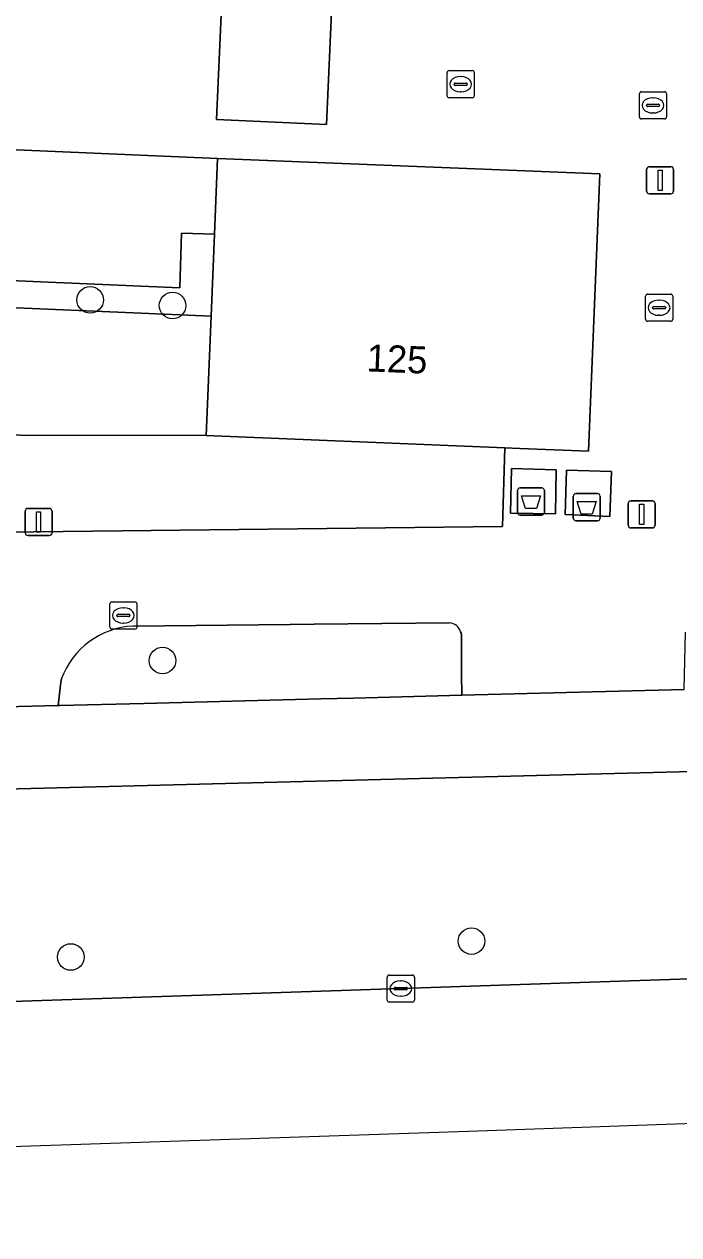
# Model space of a CAD drawing. Extents: x 160888 to 161385, y 386490 to 386908.
# Drawn here: x 161181.1 to 161205.21, y 386494.25 to 386538.84 of the extents above; entities that cross this region are included whole.
import ezdxf

# ---------------------------------------------------------------- set-up
doc = ezdxf.new("R2010")
doc.units = 0
for name, color, linetype in [('IMGEO_Afval_apart_plaats', 7, 'Continuous'), ('IMGEO_Berm_groen', 7, 'Continuous'), ('IMGEO_Boom', 7, 'Continuous'), ('IMGEO_Fietspad_gesloten', 7, 'Continuous'), ('IMGEO_Groenvoorziening', 7, 'Continuous'), ('IMGEO_Haag', 7, 'Continuous'), ('IMGEO_Kolk', 7, 'Continuous'), ('IMGEO_Lichtmast', 7, 'Continuous'), ('IMGEO_Pand', 7, 'Continuous'), ('IMGEO_Pand_nummerreeks', 7, 'Continuous'), ('IMGEO_Parkeervlak_open', 7, 'Continuous'), ('IMGEO_Rijbaan_lokaal_open', 7, 'Continuous'), ('IMGEO_Rijbaan_regionaal_gesloten', 7, 'Continuous'), ('IMGEO_Rioolput', 7, 'Continuous'), ('IMGEO_Voetgangersgebied_open', 7, 'Continuous'), ('IMGEO_Voetpad_gesloten', 7, 'Continuous')]:
    doc.layers.add(name, color=color, linetype=linetype)

msp = doc.modelspace()

# ---------------------------------------------------------------- linework, layer by layer
at = {"layer": 'IMGEO_Afval_apart_plaats'}
for p, q in [((161199.27, 386520.86), (161199.27, 386521.66)), ((161199.27, 386521.66), (161199.27, 386520.86)), ((161199.37, 386521.76), (161200.16, 386521.76)), ((161200.16, 386521.76), (161199.37, 386521.76)), ((161200.26, 386521.66), (161200.26, 386520.86)), ((161200.26, 386520.86), (161200.26, 386521.66)), ((161201.323, 386520.65), (161201.323, 386521.45)), ((161201.323, 386521.45), (161201.323, 386520.65)), ((161201.423, 386521.55), (161202.213, 386521.55)), ((161202.213, 386521.55), (161201.423, 386521.55)), ((161202.313, 386521.45), (161202.313, 386520.65)), ((161202.313, 386520.65), (161202.313, 386521.45)), ((161200.16, 386520.76), (161199.37, 386520.76)), ((161199.37, 386520.76), (161200.16, 386520.76)), ((161202.213, 386520.55), (161201.423, 386520.55)), ((161201.423, 386520.55), (161202.213, 386520.55))]:
    msp.add_line(p, q, dxfattribs=at)
for points in [[(161199.413, 386521.474), (161200.117, 386521.474), (161199.968, 386521.004), (161199.562, 386521.004), (161199.413, 386521.474)], [(161201.466, 386521.264), (161202.17, 386521.264), (161202.021, 386520.794), (161201.615, 386520.794), (161201.466, 386521.264)]]:
    msp.add_lwpolyline(points, dxfattribs=at)
for centre, start, end in [((161199.37, 386521.66), 90, 180), ((161199.37, 386521.66), 90, 180), ((161200.16, 386521.66), 0, 90), ((161200.16, 386521.66), 360, 90), ((161201.423, 386521.45), 90, 180), ((161201.423, 386521.45), 90, 180), ((161202.213, 386521.45), 0, 90), ((161202.213, 386521.45), 360, 90), ((161199.37, 386520.86), 180, 270), ((161199.37, 386520.86), 180, 270), ((161200.16, 386520.86), 270, 0), ((161200.16, 386520.86), 270, 0), ((161201.423, 386520.65), 180, 270), ((161201.423, 386520.65), 180, 270), ((161202.213, 386520.65), 270, 0), ((161202.213, 386520.65), 270, 0)]:
    msp.add_arc(centre, 0.1, start, end, dxfattribs=at)
at = {"layer": 'IMGEO_Berm_groen'}
for points in [[(161313.071, 386509.592), (161311.776, 386509.705), (161311.73, 386509.285), (161306.097, 386509.668), (161267.164, 386511.376), (161259.697, 386511.429), (161237.753, 386511.488), (161222.805, 386511.284), (161215.758, 386511.159), (161215.734, 386511.569), (161167.964, 386510.348), (161127.225, 386509.29)], [(161133.563, 386501.204), (161154.024, 386501.918), (161175.497, 386502.675), (161194.971, 386503.319), (161214.429, 386503.969), (161233.906, 386504.66), (161254.372, 386505.373), (161273.833, 386506.048), (161292.306, 386506.7), (161322.733, 386507.751)]]:
    msp.add_lwpolyline(points, dxfattribs=at)
at = {"layer": 'IMGEO_Boom'}
for centre in [(161183.527, 386528.686), (161186.565, 386528.479), (161186.191, 386515.403), (161197.575, 386505.068), (161182.817, 386504.482)]:
    msp.add_circle(centre, 0.489, dxfattribs=at)
at = {"layer": 'IMGEO_Fietspad_gesloten'}
for points in [[(161205.404, 386514.331), (161197.221, 386514.122), (161193.677, 386514.032), (161193.234, 386514.02), (161192.022, 386513.989), (161185.501, 386513.823), (161182.4, 386513.744), (161182.354, 386513.743), (161179.426, 386513.668), (161167.488, 386513.363), (161165.011, 386513.3), (161158.3, 386513.129), (161154.404, 386513.03), (161149.878, 386512.914), (161142.637, 386512.729), (161139.461, 386512.648)], [(161106.833, 386506.491), (161109.839, 386506.955), (161116.836, 386508.035), (161123.035, 386508.931), (161127.225, 386509.29), (161167.964, 386510.348), (161215.734, 386511.569), (161215.758, 386511.159), (161222.805, 386511.284), (161237.753, 386511.488), (161259.697, 386511.429), (161267.164, 386511.376), (161306.097, 386509.668), (161311.73, 386509.285), (161311.776, 386509.705), (161313.071, 386509.592)]]:
    msp.add_lwpolyline(points, dxfattribs=at)
at = {"layer": 'IMGEO_Groenvoorziening'}
for points in [[(161188.104, 386531.103), (161186.895, 386531.144), (161186.834, 386529.132), (161153.546, 386530.566), (161144.394, 386530.967), (161144.63, 386535.735), (161143.433, 386535.771), (161143.157, 386530.019), (161167.323, 386528.975), (161187.983, 386528.081)], [(161187.807, 386523.685), (161187.983, 386528.081), (161167.323, 386528.975), (161167.064, 386523.737), (161174.072, 386523.72)], [(161198.801, 386523.24), (161187.807, 386523.685), (161174.072, 386523.72), (161173.891, 386520.061), (161198.713, 386520.334)]]:
    msp.add_lwpolyline(points, close=True, dxfattribs=at)
for points in [[(161196.762, 386516.787), (161191.781, 386516.739), (161190.894, 386516.73), (161185.113, 386516.671)], [(161182.354, 386513.743), (161182.4, 386513.744), (161185.501, 386513.823), (161192.022, 386513.989), (161193.234, 386514.02), (161193.677, 386514.032), (161197.221, 386514.122), (161197.21, 386514.917), (161197.209, 386515.225), (161197.205, 386516.146), (161197.204, 386516.312), (161197.201, 386516.355), (161197.194, 386516.396), (161197.188, 386516.423), (161197.175, 386516.465)], [(161182.475, 386514.735), (161182.438, 386514.506), (161182.354, 386513.743)]]:
    msp.add_lwpolyline(points, dxfattribs=at)
for centre, radius, start, end in [((161196.737, 386516.329), 0.459, 17.2537, 86.862), ((161185.259, 386513.707), 2.967, 92.8126, 159.7365)]:
    msp.add_arc(centre, radius, start, end, dxfattribs=at)
at = {"layer": 'IMGEO_Haag'}
msp.add_lwpolyline([(161188.104, 386531.103), (161186.895, 386531.144), (161186.834, 386529.132), (161153.546, 386530.566), (161144.394, 386530.967), (161144.63, 386535.735), (161143.433, 386535.771), (161143.157, 386530.019), (161167.323, 386528.975), (161187.983, 386528.081)], close=True, dxfattribs=at)
at = {"layer": 'IMGEO_Kolk'}
for p, q in [((161196.677, 386536.204), (161196.677, 386537.056)), ((161196.752, 386537.13), (161197.604, 386537.13)), ((161197.165, 386536.91), (161197.19, 386536.91)), ((161197.678, 386537.056), (161197.678, 386536.204)), ((161196.936, 386536.624), (161196.936, 386536.636)), ((161197.374, 386536.587), (161196.976, 386536.587)), ((161196.979, 386536.673), (161197.377, 386536.673)), ((161197.188, 386536.35), (161197.163, 386536.35)), ((161197.42, 386536.636), (161197.42, 386536.624)), ((161197.604, 386536.13), (161196.752, 386536.13)), ((161203.984, 386527.972), (161203.984, 386528.824)), ((161204.059, 386528.898), (161204.911, 386528.898)), ((161204.985, 386528.824), (161204.985, 386527.972)), ((161204.243, 386528.392), (161204.243, 386528.404)), ((161204.681, 386528.355), (161204.283, 386528.355)), ((161204.286, 386528.441), (161204.684, 386528.441)), ((161204.472, 386528.678), (161204.497, 386528.678)), ((161204.727, 386528.404), (161204.727, 386528.392)), ((161204.911, 386527.898), (161204.059, 386527.898)), ((161204.495, 386528.118), (161204.47, 386528.118)), ((161184.253, 386516.637), (161184.253, 386517.489)), ((161184.328, 386517.563), (161185.18, 386517.563)), ((161184.741, 386517.343), (161184.766, 386517.343)), ((161185.254, 386517.489), (161185.254, 386516.637)), ((161184.512, 386517.057), (161184.512, 386517.069)), ((161184.95, 386517.02), (161184.552, 386517.02)), ((161184.555, 386517.106), (161184.953, 386517.106)), ((161184.764, 386516.783), (161184.739, 386516.783)), ((161184.996, 386517.069), (161184.996, 386517.057)), ((161185.18, 386516.563), (161184.328, 386516.563)), ((161194.545, 386503.819), (161195.397, 386503.819)), ((161194.47, 386502.893), (161194.47, 386503.745)), ((161194.729, 386503.313), (161194.729, 386503.325)), ((161194.772, 386503.362), (161195.17, 386503.362)), ((161194.958, 386503.599), (161194.983, 386503.599)), ((161195.213, 386503.325), (161195.213, 386503.313)), ((161195.471, 386503.745), (161195.471, 386502.893)), ((161195.167, 386503.276), (161194.769, 386503.276)), ((161194.981, 386503.039), (161194.956, 386503.039)), ((161195.397, 386502.819), (161194.545, 386502.819))]:
    msp.add_line(p, q, dxfattribs=at)
for points in [[(161196.677, 386536.204), (161196.677, 386537.056)], [(161196.752, 386537.13), (161197.604, 386537.13)], [(161197.678, 386537.056), (161197.678, 386536.204)], [(161197.604, 386536.13), (161196.752, 386536.13)], [(161203.984, 386527.972), (161203.984, 386528.824)], [(161204.059, 386528.898), (161204.911, 386528.898)], [(161204.985, 386528.824), (161204.985, 386527.972)], [(161204.911, 386527.898), (161204.059, 386527.898)], [(161184.253, 386516.637), (161184.253, 386517.489)], [(161184.328, 386517.563), (161185.18, 386517.563)], [(161185.254, 386517.489), (161185.254, 386516.637)], [(161185.18, 386516.563), (161184.328, 386516.563)], [(161194.545, 386503.819), (161195.397, 386503.819)], [(161194.47, 386502.893), (161194.47, 386503.745)], [(161195.471, 386503.745), (161195.471, 386502.893)], [(161195.397, 386502.819), (161194.545, 386502.819)]]:
    msp.add_lwpolyline(points, dxfattribs=at)
for centre, radius, start, end in [((161196.754, 386537.054), 0.0765, 91.552, 178.448), ((161196.754, 386537.054), 0.0765, 91.552, 178.448), ((161197.602, 386537.054), 0.0765, 1.552, 88.448), ((161197.602, 386537.054), 0.0765, 1.552, 88.448), ((161196.976, 386536.633), 0.0403, 85.8775, 175.7526), ((161196.973, 386536.623), 0.0366, 178.938, 274.7102), ((161197.377, 386536.63), 0.043, 264.8664, 352.4533), ((161197.381, 386536.635), 0.0386, 1.7309, 96.639), ((161196.754, 386536.206), 0.0765, 181.552, 268.448), ((161196.754, 386536.206), 0.0765, 181.552, 268.448), ((161197.602, 386536.206), 0.0765, 271.552, 358.448), ((161197.602, 386536.206), 0.0765, 271.552, 358.448), ((161204.061, 386528.822), 0.0765, 91.552, 178.448), ((161204.061, 386528.822), 0.0765, 91.552, 178.448), ((161204.909, 386528.822), 0.0765, 1.552, 88.448), ((161204.909, 386528.822), 0.0765, 1.552, 88.448), ((161204.283, 386528.401), 0.0403, 85.8775, 175.7526), ((161204.28, 386528.391), 0.0366, 178.938, 274.7102), ((161204.684, 386528.398), 0.043, 264.8664, 352.4533), ((161204.688, 386528.403), 0.0386, 1.7309, 96.639), ((161204.061, 386527.974), 0.0765, 181.552, 268.448), ((161204.061, 386527.974), 0.0765, 181.552, 268.448), ((161204.909, 386527.974), 0.0765, 271.552, 358.448), ((161204.909, 386527.974), 0.0765, 271.552, 358.448), ((161184.33, 386517.487), 0.0765, 91.552, 178.448), ((161184.33, 386517.487), 0.0765, 91.552, 178.448), ((161185.178, 386517.487), 0.0765, 1.552, 88.448), ((161185.178, 386517.487), 0.0765, 1.552, 88.448), ((161184.552, 386517.066), 0.0403, 85.8775, 175.7526), ((161184.549, 386517.056), 0.0366, 178.938, 274.7102), ((161184.953, 386517.063), 0.043, 264.8664, 352.4533), ((161184.957, 386517.068), 0.0386, 1.7309, 96.639), ((161184.33, 386516.639), 0.0765, 181.552, 268.448), ((161184.33, 386516.639), 0.0765, 181.552, 268.448), ((161185.178, 386516.639), 0.0765, 271.552, 358.448), ((161185.178, 386516.639), 0.0765, 271.552, 358.448), ((161194.547, 386503.743), 0.0765, 91.552, 178.448), ((161194.547, 386503.743), 0.0765, 91.552, 178.448), ((161195.395, 386503.743), 0.0765, 1.552, 88.448), ((161195.395, 386503.743), 0.0765, 1.552, 88.448), ((161194.769, 386503.322), 0.0403, 85.8775, 175.7526), ((161195.174, 386503.324), 0.0386, 1.7309, 96.639), ((161194.547, 386502.895), 0.0765, 181.552, 268.448), ((161194.547, 386502.895), 0.0765, 181.552, 268.448), ((161194.766, 386503.312), 0.0366, 178.938, 274.7102), ((161195.17, 386503.319), 0.043, 264.8664, 352.4533), ((161195.395, 386502.895), 0.0765, 271.552, 358.448), ((161195.395, 386502.895), 0.0765, 271.552, 358.448)]:
    msp.add_arc(centre, radius, start, end, dxfattribs=at)
for centre, major_axis, ratio, start_param, end_param in [((161197.164, 386536.63), (-0.387, 0.002), 0.722429, 4.712389, 7.853982), ((161197.189, 386536.63), (-0.39, 0.002), 0.717154, 1.570796, 4.712389), ((161204.471, 386528.398), (-0.387, 0.002), 0.722429, 4.712389, 7.853982), ((161204.496, 386528.398), (-0.39, 0.002), 0.717154, 1.570796, 4.712389), ((161184.74, 386517.063), (-0.387, 0.002), 0.722429, 4.712389, 7.853982), ((161184.765, 386517.063), (-0.39, 0.002), 0.717154, 1.570796, 4.712389), ((161194.957, 386503.319), (-0.387, 0.002), 0.722429, 4.712389, 7.853982), ((161194.982, 386503.319), (-0.39, 0.002), 0.717154, 1.570796, 4.712389)]:
    msp.add_ellipse(centre, major_axis=major_axis, ratio=ratio, start_param=start_param, end_param=end_param, dxfattribs=at)
at = {"layer": 'IMGEO_Lichtmast'}
for p, q in [((161204.025, 386532.692), (161204.025, 386533.492)), ((161204.025, 386533.492), (161204.025, 386532.692)), ((161204.125, 386533.592), (161204.915, 386533.592)), ((161204.915, 386533.592), (161204.125, 386533.592)), ((161205.015, 386533.492), (161205.015, 386532.692)), ((161205.015, 386532.692), (161205.015, 386533.492)), ((161204.915, 386532.592), (161204.125, 386532.592)), ((161204.125, 386532.592), (161204.915, 386532.592)), ((161203.346, 386520.385), (161203.346, 386521.185)), ((161203.346, 386521.185), (161203.346, 386520.385)), ((161203.446, 386521.285), (161204.236, 386521.285)), ((161204.236, 386521.285), (161203.446, 386521.285)), ((161204.336, 386521.185), (161204.336, 386520.385)), ((161204.336, 386520.385), (161204.336, 386521.185)), ((161181.135, 386520.106), (161181.135, 386520.906)), ((161181.135, 386520.906), (161181.135, 386520.106)), ((161181.235, 386521.006), (161182.025, 386521.006)), ((161182.025, 386521.006), (161181.235, 386521.006)), ((161182.125, 386520.906), (161182.125, 386520.106)), ((161182.125, 386520.106), (161182.125, 386520.906)), ((161204.236, 386520.285), (161203.446, 386520.285)), ((161203.446, 386520.285), (161204.236, 386520.285)), ((161182.025, 386520.006), (161181.235, 386520.006)), ((161181.235, 386520.006), (161182.025, 386520.006))]:
    msp.add_line(p, q, dxfattribs=at)
for points in [[(161204.445, 386533.467), (161204.595, 386533.467), (161204.595, 386532.717), (161204.445, 386532.717), (161204.445, 386533.467)], [(161203.766, 386521.16), (161203.916, 386521.16), (161203.916, 386520.41), (161203.766, 386520.41), (161203.766, 386521.16)], [(161181.555, 386520.881), (161181.705, 386520.881), (161181.705, 386520.131), (161181.555, 386520.131), (161181.555, 386520.881)]]:
    msp.add_lwpolyline(points, dxfattribs=at)
for centre, start, end in [((161204.125, 386533.492), 90, 180), ((161204.125, 386533.492), 90, 180), ((161204.915, 386533.492), 0, 90), ((161204.915, 386533.492), 360, 90), ((161204.125, 386532.692), 180, 270), ((161204.125, 386532.692), 180, 270), ((161204.915, 386532.692), 270, 0), ((161204.915, 386532.692), 270, 0), ((161203.446, 386521.185), 90, 180), ((161203.446, 386521.185), 90, 180), ((161204.236, 386521.185), 0, 90), ((161204.236, 386521.185), 360, 90), ((161181.235, 386520.906), 90, 180), ((161181.235, 386520.906), 90, 180), ((161182.025, 386520.906), 0, 90), ((161182.025, 386520.906), 360, 90), ((161203.446, 386520.385), 180, 270), ((161203.446, 386520.385), 180, 270), ((161204.236, 386520.385), 270, 0), ((161204.236, 386520.385), 270, 0), ((161181.235, 386520.106), 180, 270), ((161181.235, 386520.106), 180, 270), ((161182.025, 386520.106), 270, 0), ((161182.025, 386520.106), 270, 0)]:
    msp.add_arc(centre, 0.1, start, end, dxfattribs=at)
at = {"layer": 'IMGEO_Pand'}
msp.add_lwpolyline([(161202.3, 386533.324), (161188.216, 386533.895), (161188.104, 386531.103), (161187.983, 386528.081), (161187.807, 386523.685), (161198.801, 386523.24), (161199.357, 386523.218), (161201.885, 386523.116)], close=True, dxfattribs=at)
at = {"layer": 'IMGEO_Parkeervlak_open'}
msp.add_lwpolyline([(161188.216, 386533.895), (161153.751, 386535.376), (161153.546, 386530.566), (161186.834, 386529.132), (161186.895, 386531.144), (161188.104, 386531.103)], close=True, dxfattribs=at)
at = {"layer": 'IMGEO_Rijbaan_lokaal_open'}
msp.add_lwpolyline([(161192.481, 386540.666), (161188.431, 386540.847), (161188.185, 386535.33), (161192.235, 386535.149)], close=True, dxfattribs=at)
at = {"layer": 'IMGEO_Rijbaan_regionaal_gesloten'}
msp.add_lwpolyline([(161083.554, 386494.25), (161197.468, 386498.064), (161264.673, 386500.448), (161323.284, 386502.509), (161323.08, 386507.769), (161322.733, 386507.751), (161292.306, 386506.7), (161273.833, 386506.048), (161254.372, 386505.373), (161233.906, 386504.66), (161214.429, 386503.969), (161194.971, 386503.319), (161175.497, 386502.675), (161154.024, 386501.918), (161133.563, 386501.204)], dxfattribs=at)
at = {"layer": 'IMGEO_Rioolput'}
for p, q in [((161203.834, 386536.351), (161204.686, 386536.351)), ((161203.759, 386535.425), (161203.759, 386536.277)), ((161204.061, 386535.894), (161204.459, 386535.894)), ((161204.247, 386536.131), (161204.272, 386536.131)), ((161204.76, 386536.277), (161204.76, 386535.425)), ((161204.018, 386535.845), (161204.018, 386535.857)), ((161204.456, 386535.808), (161204.058, 386535.808)), ((161204.27, 386535.571), (161204.245, 386535.571)), ((161204.502, 386535.857), (161204.502, 386535.845)), ((161204.686, 386535.351), (161203.834, 386535.351))]:
    msp.add_line(p, q, dxfattribs=at)
for points in [[(161203.834, 386536.351), (161204.686, 386536.351)], [(161203.759, 386535.425), (161203.759, 386536.277)], [(161204.76, 386536.277), (161204.76, 386535.425)], [(161204.686, 386535.351), (161203.834, 386535.351)]]:
    msp.add_lwpolyline(points, dxfattribs=at)
for centre, radius, start, end in [((161203.836, 386536.275), 0.0765, 91.552, 178.448), ((161203.836, 386536.275), 0.0765, 91.552, 178.448), ((161204.684, 386536.275), 0.0765, 1.552, 88.448), ((161204.684, 386536.275), 0.0765, 1.552, 88.448), ((161204.058, 386535.854), 0.0403, 85.8775, 175.7526), ((161204.463, 386535.856), 0.0386, 1.7309, 96.639), ((161203.836, 386535.427), 0.0765, 181.552, 268.448), ((161203.836, 386535.427), 0.0765, 181.552, 268.448), ((161204.055, 386535.844), 0.0366, 178.938, 274.7102), ((161204.459, 386535.851), 0.043, 264.8664, 352.4533), ((161204.684, 386535.427), 0.0765, 271.552, 358.448), ((161204.684, 386535.427), 0.0765, 271.552, 358.448)]:
    msp.add_arc(centre, radius, start, end, dxfattribs=at)
for centre, major_axis, ratio, start_param, end_param in [((161204.246, 386535.851), (-0.387, 0.002), 0.722429, 4.712389, 7.853982), ((161204.271, 386535.851), (-0.39, 0.002), 0.717154, 1.570796, 4.712389)]:
    msp.add_ellipse(centre, major_axis=major_axis, ratio=ratio, start_param=start_param, end_param=end_param, dxfattribs=at)
at = {"layer": 'IMGEO_Voetgangersgebied_open'}
for points in [[(161192.235, 386535.149), (161188.185, 386535.33), (161188.431, 386540.847), (161192.481, 386540.666)], [(161201.885, 386523.116), (161199.357, 386523.218), (161198.801, 386523.24), (161198.713, 386520.334), (161173.891, 386520.061), (161152.345, 386519.823), (161148.719, 386523.784), (161143.15, 386529.865), (161143.157, 386530.019), (161143.433, 386535.771), (161144.63, 386535.735), (161144.394, 386530.967), (161153.546, 386530.566), (161153.751, 386535.376), (161188.216, 386533.895), (161202.3, 386533.324)], [(161199.042, 386522.473), (161200.688, 386522.428), (161200.666, 386520.805), (161199.008, 386520.826)], [(161201.026, 386520.776), (161201.068, 386522.41), (161202.736, 386522.365), (161202.666, 386520.71)]]:
    msp.add_lwpolyline(points, close=True, dxfattribs=at)
for points in [[(161185.113, 386516.671), (161190.894, 386516.73), (161191.781, 386516.739), (161196.762, 386516.787)], [(161197.175, 386516.465), (161197.188, 386516.423), (161197.194, 386516.396), (161197.201, 386516.355), (161197.204, 386516.312), (161197.205, 386516.146), (161197.209, 386515.225), (161197.21, 386514.917), (161197.221, 386514.122), (161205.404, 386514.331), (161205.457, 386516.449)], [(161179.426, 386513.668), (161182.354, 386513.743), (161182.438, 386514.506), (161182.475, 386514.735)]]:
    msp.add_lwpolyline(points, dxfattribs=at)
for centre, radius, start, end in [((161196.737, 386516.329), 0.459, 17.2537, 86.862), ((161185.259, 386513.707), 2.967, 92.8126, 159.7365)]:
    msp.add_arc(centre, radius, start, end, dxfattribs=at)
at = {"layer": 'IMGEO_Voetpad_gesloten'}
for points in [[(161199.042, 386522.473), (161199.008, 386520.826), (161200.666, 386520.805), (161200.688, 386522.428)], [(161201.026, 386520.776), (161202.666, 386520.71), (161202.736, 386522.365), (161201.068, 386522.41)]]:
    msp.add_lwpolyline(points, close=True, dxfattribs=at)

# ---------------------------------------------------------------- texts
at = {"layer": 'IMGEO_Pand_nummerreeks'}
msp.add_text('125', height=1, rotation=357.6738, dxfattribs=at).set_placement((161193.7, 386526.055))

doc.saveas('drawing.dxf')
